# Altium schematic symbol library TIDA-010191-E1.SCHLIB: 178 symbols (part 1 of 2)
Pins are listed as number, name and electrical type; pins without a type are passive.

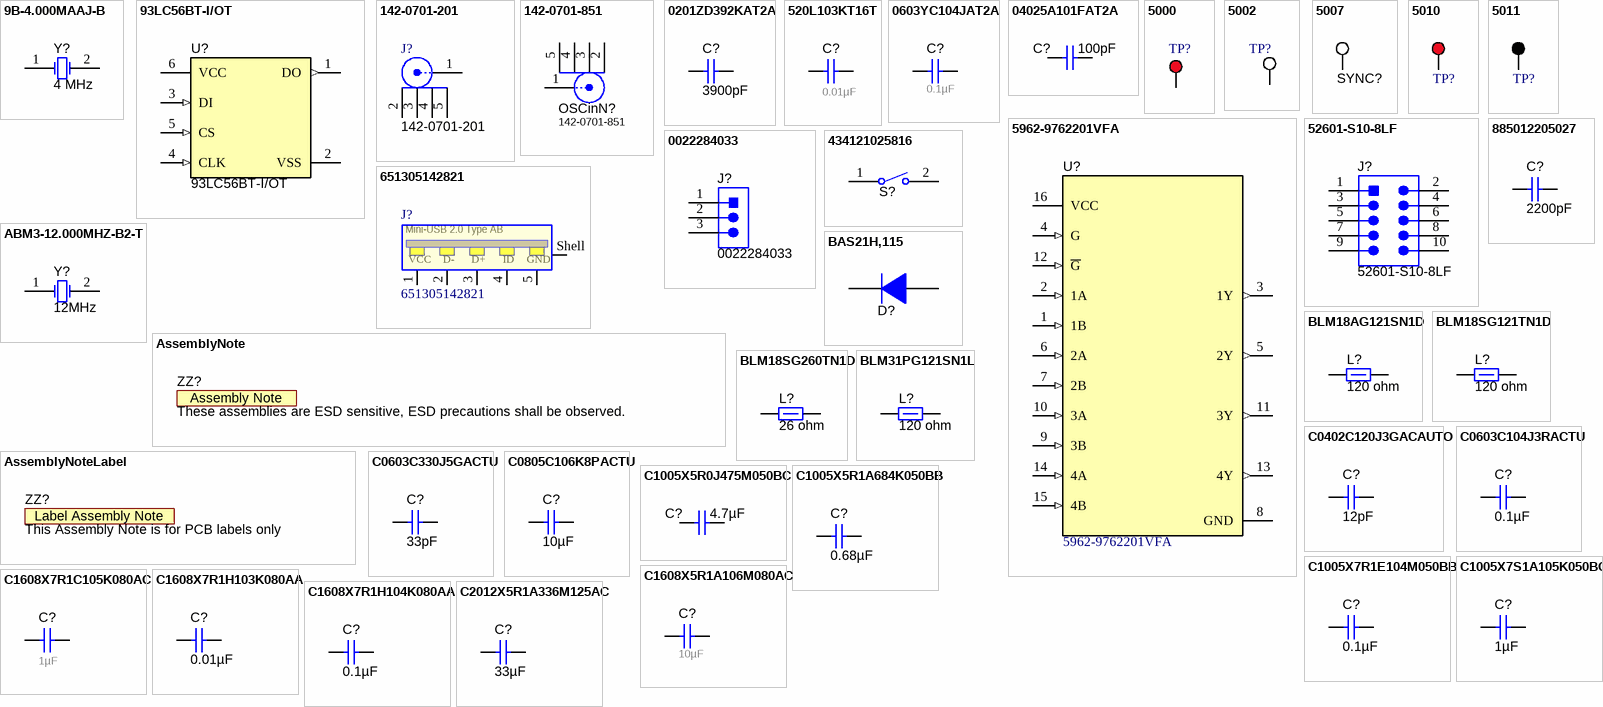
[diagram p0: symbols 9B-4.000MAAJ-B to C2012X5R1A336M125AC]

## 9B-4.000MAAJ-B
designator Y?  Frequency_Fixed: 4 MHz  (hidden comment: 9B-4.000MAAJ-B)
Crystal, 4 MHz, 18 pF, TH; Manufacturer: TXC Corporation; SymbolCreator: a0412235; SizeAreaWB_mm2: 94.5; SizeArea_mm2: 57.5; SizeX_mm: 11.5; SizeY_mm: 5; SizeZ_mm: 3.68; U/M: EA; TaMin_C: -20; TaMax_C: 70; Frequency Stability: ±30ppm
footprint TXC_9B
pins: 1 OSC1, 2 OSC2

## 93LC56BT-I/OT
designator U?
2K Microwire Compatible Serial EEPROM, SOT-23-6; Manufacturer: Microchip; SymbolCreator: x0208326; SizeAreaWB_mm2: 14.82; SizeArea_mm2: 8.12; SizeX_mm: 2.9; SizeY_mm: 2.8; SizeZ_mm: 1.15
footprint SOT-23-6
pins: 1 DO (out), 2 VSS (power), 3 DI (in), 4 CLK (in), 5 CS (in), 6 VCC (power)

## 142-0701-201
designator J?
Connector, TH, SMA; Manufacturer: Emerson Network Power; SymbolCreator: X0208326
footprint Johnson_142-0701-20x (Johnson Components recommended land pattern)
pins: 1, 2, 3, 4, 5

## 142-0701-851
designator OSCinN?
Connector, SMT, End launch SMA 50 ohm; Manufacturer: Emerson Network Power Connectivity; U/M: EA
footprint EMERSON_142-0701-851 (Johnson Components)
pins: 1, 2, 3, 4, 5

## 0201ZD392KAT2A
designator C?  ValueDisplayed: 3900pF  (hidden comment: 0201ZD392KAT2A)
CAP, CERM, 3900 pF, 10 V, +/- 10%, X5R, 0201; Manufacturer: AVX; Polarized: N; CompType: Capacitor; Value: 3900pF; U/M: EA; Cap_F: 0.0000000039; Tolerance_%: 10; Value1: Unknown; Value2: 10V; TaMin_C: -55; TaMax_C: 85; Cap_Case: 0201; SizeArea_mm2: 0.18; SizeAreaWB_mm2: 2.08; SizeX_mm: 0.6; SizeY_mm: 0.3; SizeZ_mm: 0.26; AEC Category: Q200
signal-integrity model Cap
simulation model Cap
footprint 0201
footprint 0201M
footprint 0201L
footprint 0201_Silk
pins: 1, 2

## 520L103KT16T
designator C?  ValueDisplayed: 0.01µF  (hidden comment: 520L103KT16T)
CAP, CERM, 0.01 µF, 16 V, +/- 10%, X7R, 0402; Manufacturer: AT Ceramics; Polarized: N; CompType: Capacitor; Value: 0.01uF; U/M: EA; Cap_F: 0.00000001; Tolerance_%: 10; Value1: Unknown; VDC_V: 16; Value2: 16V; TaMin_C: -55; TaMax_C: 125; Cap_Case: 0402; AEC Category: Q200; SizeArea_mm2: 0.5; SizeAreaWB_mm2: 3; SizeX_mm: 1; SizeZ_mm: 0.65
signal-integrity model Cap
simulation model Cap
footprint 0402_065
footprint 0402_065M
footprint 0402_065L
footprint 0402_065S
pins: 1, 2

## 0603YC104JAT2A
designator C?  ValueDisplayed: 0.1µF  (hidden comment: 0603YC104JAT2A)
CAP, CERM, 0.1uF, 16V, +/-5%, X7R, 0603; Manufacturer: AVX; Cap_Case: 0603; ESR_Ohm: 0.039; Polarized: N; TaMax_C: 125; TaMin_C: -55; Tolerance_%: 5; VDC_V: 16; Cap_F: 0.0000001; CompType: Capacitor; Value1: 0.039 ohm; U/M: EA
signal-integrity model Cap
simulation model Cap
footprint 0603
footprint 0603M
footprint 0603L
footprint 0603_HV
pins: 1, 2

## 04025A101FAT2A
designator C?  ValueDisplayed: 100pF  (hidden comment: 04025A101FAT2A)
CAP, CERM, 100 pF, 50 V, +/- 1%, C0G/NP0, 0402; Manufacturer: AVX; Polarized: N; CompType: Capacitor; Value: 100pF; U/M: EA; Cap_F: 0.0000000001; Tolerance_%: 1; Value1: Unknown; VDC_V: 50; Value2: 50V; TaMin_C: -55; TaMax_C: 125; Cap_Case: 0402; SizeArea_mm2: 0.5; SizeAreaWB_mm2: 3; SizeZ_mm: 0.6; AEC Category: Q200
signal-integrity model Cap
simulation model Cap
footprint 0402
footprint 0402M
footprint 0402L
footprint 0402S
pins: 1, 2

## 5000
designator TP?  (value not drawn)
Test Point, Miniature, Red, TH; Manufacturer: Keystone; CompType: Test Point Loop; ContactFinish: Silver
footprint Keystone5000
pins: 1

## 5002
designator TP?  (value not drawn)
Test Point, Miniature, White, TH; Manufacturer: Keystone; CompType: Test Point Loop; ContactFinish: Silver; Green_Lifecycle: Active; Green_REACh: Passed
footprint Keystone5002
pins: 1

## 5007
designator SYNC?  (value not drawn)
Test Point, Compact, White, TH; Manufacturer: Keystone; CompType: Test Point Loop; U/M: EA
footprint Keystone5007
pins: 1

## 5010
designator TP?  (value not drawn)
Test Point, Multipurpose, Red, TH; Manufacturer: Keystone; CompType: Test Point Loop; ContactFinish: Silver
footprint Keystone5010
pins: 1

## 5011
designator TP?  (value not drawn)
Test Point, Multipurpose, Black, TH; Manufacturer: Keystone; CompType: Test Point Loop; ContactFinish: Silver
footprint Keystone5011
pins: 1

## 5962-9762201VFA
designator U?
Quad LVDS Receiver, W0016A (CFP-16); Manufacturer: Texas Instruments; SizeZ_mm: 2.03; AEC Category: Q200; CompType: IC; AEC Qualified: N; Rating: Space
footprint W0016A_Custom_A (DFP, 16 Leads, Body 10.2x6.7mm, Pitch 1.27mm, Gullwing Leadform)
pins: 1 1B (in), 2 1A (in), 3 1Y (out), 4 G (in), 5 2Y (out), 6 2A (in), 7 2B (in), 8 GND (power), 9 3B (in), 10 3A (in), 11 3Y (out), 12 ~{G} (in), 13 4Y (out), 14 4A (in), 15 4B (in), 16 VCC (power)

## 52601-S10-8LF
designator J?
Header (shrouded), 100mil, 5x2, Gold, SMT; Manufacturer: FCI; SymbolCreator: a0412235
footprint FCI_52601-S10-8LF (FCI Electronics)
pins: 1, 2, 3, 4, 5, 6, 7, 8, 9, 10

## 0022284033
designator J?
Header, 2.54mm, 3x1, Tin, TH; Manufacturer: Molex; SymbolCreator: a0799628; Pitch_mm: 2.54; Gender: Male; Shrouded: N; Row_Count: 1; Current_A: 4; Voltage_V: 250; Cert_UL: Y
footprint Molex_0022284033
pins: 1, 2, 3
3 alternate drawings of the same symbol

## 434121025816
designator S?  (value not drawn)
Switch, Tactile, SPST, 12 V, SMD; Manufacturer: Wurth Elektronik; SymbolCreator: a0799628; VDC_V: 12; SwitchFunction: Off-On; PositionCount: 1; CurrentRating_mA: 50
footprint SW_434121025816
pins: 1, 2

## 651305142821
designator J?
WR-COM Mini USB 2.0 Type AB SMT Horizontal 5 Contacts
footprint 651305142821 (5 pins)
pins: 1 VCC, 2 D-, 3 D+, 4 ID, 5 GND, Shell

## 885012205027
designator C?  ValueDisplayed: 2200pF  (hidden comment: 885012205027)
CAP, CERM, 2200 pF, 16 V,+/- 10%, X7R, 0402; Manufacturer: Wurth Elektronik; Polarized: N; CompType: Capacitor; Value: 2200pF; U/M: EA; Cap_F: 0.0000000022; Tolerance_%: 10; VDC_V: 16; Value2: 16V; TaMin_C: -55; TaMax_C: 125; Cap_Case: 0402; AEC Category: Q200; SizeArea_mm2: 0.5; SizeAreaWB_mm2: 3; SizeX_mm: 1; SizeZ_mm: 0.6
signal-integrity model Cap
simulation model Cap
footprint 0402
footprint 0402M
footprint 0402L
footprint 0402S
pins: 1, 2

## ABM3-12.000MHZ-B2-T
designator Y?  Frequency: 12MHz  (hidden comment: ABM3-12.000MHZ-B2-T)
Crystal, 12Mhz, 18pF, SMD; Manufacturer: Abracon Corporation; SymbolCreator: a0412235; U/M: EA; TaMin_C: -20; TaMax_C: 70; Frequency Stability: ±50ppm
footprint XTAL_ABM3
pins: 1 OSC1, 2 OSC2

## AssemblyNote
designator ZZ?, comment These assemblies are ESD sensitive, ESD precautions shall be observed.  (no BOM)
SymbolCreator: codlsc; CompType: AssemblyNote
footprint AssemblyNote

## AssemblyNoteLabel
designator ZZ?, comment This Assembly Note is for PCB labels only  (no BOM)
SymbolCreator: a0412235
footprint AssemblyNoteLabel

## BAS21H,115
designator D?  (value not drawn)
Diode, Standard Recovery Rectifier, 200 V, 0.2 A, SOD-123F; Manufacturer: Nexperia; U/M: EA; Vf_V: 1.25; Value: 200V; Value1: 0.2A; Value2: 1.25V; Io_A: 0.2; Vr_V: 200; TJmax_C: 150; SizeAreaWB_mm2: 11.7; SizeArea_mm2: 5.6; SizeX_mm: 3.5; SizeY_mm: 1.6; SizeZ_mm: 1.1; AEC Category: Q101; AEC Qualified: N; Green_Lifecycle: Not Set; Green_REACh: Incomplete
signal-integrity model Diode
footprint SOD-123F
pins: 1 K, 2 A

## BLM18AG121SN1D
designator L?  ValueDisplayed: 120 ohm  (hidden comment: BLM18AG121SN1D)
Ferrite Bead, 120 ohm @ 100 MHz, 0.5 A, 0603; Manufacturer: MuRata; Value: 120 ohm; Imax_A: 0.5; DCR_ohm: 0.18; Value1: 0.18 ohm; Value2: 0.5A; SizeAreaWB_mm2: 4.68; SizeArea_mm2: 1.28; SizeX_mm: 1.6; SizeY_mm: 0.8; SizeZ_mm: 1; ZTyp@100MHz_Ohm: 120
footprint 0603
footprint 0603M
footprint 0603L
footprint 0603_HV
footprint 0603S
pins: 1, 2

## BLM18SG121TN1D
designator L?  ValueDisplayed: 120 ohm  (hidden comment: BLM18SG121TN1D)
Ferrite Bead, 120 ohm @ 100 MHz, 3 A, 0603; Manufacturer: MuRata; Value: 120 ohm; Imax_A: 3; DCR_ohm: 0.025; Value1: 0.025 ohm; Value2: 3A; SizeAreaWB_mm2: 4.68; SizeArea_mm2: 1.28; SizeX_mm: 1.6; SizeY_mm: 0.8; SizeZ_mm: 1; ZTyp@100MHz_Ohm: 120
footprint 0603
footprint 0603M
footprint 0603L
footprint 0603_HV
footprint 0603S
pins: 1, 2

## BLM18SG260TN1D
designator L?  ValueDisplayed: 26 ohm  (hidden comment: BLM18SG260TN1D)
Ferrite Bead, 26 ohm @ 100 MHz, 6 A, 0603; Manufacturer: MuRata; Value: 26 ohm; Imax_A: 6; DCR_ohm: 0.007; Value1: 0.007 ohm; Value2: 6A; SizeAreaWB_mm2: 4.68; SizeArea_mm2: 1.28; SizeX_mm: 1.6; SizeY_mm: 0.8; SizeZ_mm: 1; ZTyp@100MHz_Ohm: 26
footprint 0603
footprint 0603M
footprint 0603L
footprint 0603_HV
footprint 0603S
pins: 1, 2

## BLM31PG121SN1L
designator L?  ValueDisplayed: 120 ohm  (hidden comment: BLM31PG121SN1L)
Ferrite Bead, 120 ohm @ 100 MHz, 3.5 A, 1206; Manufacturer: MuRata; Value: 120 ohm; Imax_A: 3.5; DCR_ohm: 0.02; Value1: 0.02 ohm; Value2: 3.5A; SizeAreaWB_mm2: 10.92; SizeArea_mm2: 5.12; SizeX_mm: 3.2; SizeY_mm: 1.6; SizeZ_mm: 1.35; ZTyp@100MHz_Ohm: 120
footprint 1206
footprint 1206M
footprint 1206L
pins: 1, 2

## C0402C120J3GACAUTO
designator C?  ValueDisplayed: 12pF  (hidden comment: C0402C120J3GACAUTO)
CAP, CERM, 12 pF, 25 V, +/- 5%, C0G/NP0, AEC-Q200 Grade 1, 0402; Manufacturer: Kemet; Polarized: N; CompType: Capacitor; Value: 12pF; U/M: EA; Cap_F: 0.000000000012; Tolerance_%: 5; Value1: Unknown; VDC_V: 25; Value2: 25V; TaMin_C: -55; TaMax_C: 125; Cap_Case: 0402; SizeArea_mm2: 0.5; SizeAreaWB_mm2: 3; SizeX_mm: 1; SizeZ_mm: 0.6; AEC Category: Q200; AEC Qualified: Y
signal-integrity model Cap
simulation model Cap
footprint 0402
footprint 0402M
footprint 0402L
footprint 0402S
pins: 1, 2

## C0603C104J3RACTU
designator C?  ValueDisplayed: 0.1µF  (hidden comment: C0603C104J3RACTU)
CAP, CERM, 0.1uF, 25V, +/-5%, X7R, 0603; Manufacturer: Kemet; Cap_Case: 0603; Polarized: N; TaMax_C: 125; TaMin_C: -55; Tolerance_%: 5; VDC_V: 25; Cap_F: 0.0000001; CompType: Capacitor; Value1: Unknown; U/M: EA
signal-integrity model Cap
simulation model Cap
footprint 0603
footprint 0603M
footprint 0603L
footprint 0603_HV
pins: 1, 2

## C0603C330J5GACTU
designator C?  ValueDisplayed: 33pF  (hidden comment: C0603C330J5GACTU)
CAP, CERM, 33pF, 50V, +/-5%, C0G/NP0, 0603; Manufacturer: Kemet; Cap_Case: 0603; Polarized: N; TaMax_C: 125; TaMin_C: -55; Tolerance_%: 5; VDC_V: 50; Cap_F: 0.000000000033; CompType: Capacitor; U/M: EA; Value1: Unknown
signal-integrity model Cap
simulation model Cap
footprint 0603
footprint 0603M
footprint 0603L
footprint 0603_HV
pins: 1, 2

## C0805C106K8PACTU
designator C?  ValueDisplayed: 10µF  (hidden comment: C0805C106K8PACTU)
CAP, CERM, 10uF, 10V, +/-10%, X5R, 0805; Manufacturer: Kemet; Cap_Case: 0805; ESR_Ohm: 0.003; IRMS_A: 11.43; Polarized: N; TaMax_C: 85; TaMin_C: -55; Tolerance_%: 10; Cap_F: 0.00001; CompType: Capacitor; Value1: 0.003 ohm; U/M: EA
signal-integrity model Cap
simulation model Cap
footprint 0805_HV
footprint 0805
footprint 0805M
footprint 0805L
pins: 1, 2

## C1005X5R0J475M050BC
designator C?  ValueDisplayed: 4.7µF  (hidden comment: C1005X5R0J475M050BC)
CAP, CERM, 4.7 µF, 6.3 V, +/- 20%, X5R, 0402; Manufacturer: TDK; Polarized: N; CompType: Capacitor; Value: 4.7uF; U/M: EA; Cap_F: 0.0000047; Tolerance_%: 20; Value1: Unknown; VDC_V: 6.3; Value2: 6.3V; TaMin_C: -55; TaMax_C: 85; Cap_Case: 0402; SizeArea_mm2: 0.5; SizeAreaWB_mm2: 3; SizeX_mm: 1; SizeZ_mm: 0.6; AEC Category: Q200
signal-integrity model Cap
simulation model Cap
footprint 0402
footprint 0402M
footprint 0402L
footprint 0402S
pins: 1, 2

## C1005X5R1A684K050BB
designator C?  ValueDisplayed: 0.68µF  (hidden comment: C1005X5R1A684K050BB)
CAP, CERM, 0.68 µF, 10 V, +/- 10%, X5R, 0402; Manufacturer: TDK; Polarized: N; CompType: Capacitor; Value: 0.68uF; U/M: EA; Cap_F: 0.00000068; Tolerance_%: 10; Value1: Unknown; Value2: 10V; TaMin_C: -55; TaMax_C: 85; Cap_Case: 0402; SizeArea_mm2: 0.5; SizeAreaWB_mm2: 3; SizeX_mm: 1; SizeZ_mm: 0.6; AEC Category: Q200
signal-integrity model Cap
simulation model Cap
footprint 0402
footprint 0402M
footprint 0402L
footprint 0402S
pins: 1, 2

## C1005X7R1E104M050BB
designator C?  ValueDisplayed: 0.1µF  (hidden comment: C1005X7R1E104M050BB)
CAP, CERM, 0.1 µF, 25 V, +/- 20%, X7R, 0402; Manufacturer: TDK; Cap_Case: 0402; Polarized: N; TaMax_C: 125; TaMin_C: -55; Tolerance_%: 20; VDC_V: 25; Cap_F: 0.0000001; CompType: Capacitor; Value: 0.1uF; Value1: Unknown; Value2: 25V; U/M: EA; SizeArea_mm2: 0.5; SizeAreaWB_mm2: 3; SizeX_mm: 1; SizeZ_mm: 0.6; AEC Category: Q200
signal-integrity model Cap
simulation model Cap
footprint 0402
footprint 0402M
footprint 0402L
footprint 0402S
pins: 1, 2

## C1005X7S1A105K050BC
designator C?  ValueDisplayed: 1µF  (hidden comment: C1005X7S1A105K050BC)
CAP, CERM, 1 µF, 10 V, +/- 10%, X7S, 0402; Manufacturer: TDK; Polarized: N; CompType: Capacitor; Value: 1uF; U/M: EA; Cap_F: 0.000001; Tolerance_%: 10; ESR_ohm: 0.011416; Value1: 0.011416 ohm; Value2: 10V; IRMS_A: 1.483; TaMin_C: -55; TaMax_C: 125; Cap_Case: 0402; SizeArea_mm2: 0.5; SizeAreaWB_mm2: 3; SizeX_mm: 1; SizeZ_mm: 0.6; AEC Category: Q200
signal-integrity model Cap
simulation model Cap
footprint 0402
footprint 0402M
footprint 0402L
footprint 0402S
pins: 1, 2

## C1608X5R1A106M080AC
designator C?  ValueDisplayed: 10µF  (hidden comment: C1608X5R1A106M080AC)
CAP, CERM, 10 µF, 10 V, +/- 20%, X5R, 0603; Manufacturer: TDK; Cap_Case: 0603; ESR_ohm: 0.0078; IRMS_A: 1.85; Polarized: N; TaMax_C: 85; TaMin_C: -55; Tolerance_%: 20; VDC_V: 10; Cap_F: 0.00001; CompType: Capacitor; Value: 10uF; U/M: EA; Value1: 0.0078 ohm; Value2: 10V; AEC Category: Q200
signal-integrity model Cap
simulation model Cap
footprint 0603
footprint 0603M
footprint 0603L
footprint 0603_HV
footprint 0603S
pins: 1, 2

## C1608X7R1C105K080AC
designator C?  ValueDisplayed: 1µF  (hidden comment: C1608X7R1C105K080AC)
CAP, CERM, 1 µF, 16 V, +/- 10%, X7R, 0603; Manufacturer: TDK; Cap_Case: 0603; ESR_ohm: 0.0057; Polarized: N; TaMax_C: 125; TaMin_C: -55; Tolerance_%: 10; VDC_V: 16; Cap_F: 0.000001; CompType: Capacitor; Value: 1uF; Value1: 0.0057 ohm; Value2: 16V; U/M: EA; SizeArea_mm2: 1.28; SizeAreaWB_mm2: 4.68; SizeX_mm: 1.6; SizeY_mm: 0.8; SizeZ_mm: 1; AEC Category: Q200
signal-integrity model Cap
simulation model Cap
footprint 0603
footprint 0603M
footprint 0603L
footprint 0603_HV
footprint 0603S
pins: 1, 2

## C1608X7R1H103K080AA
designator C?  ValueDisplayed: 0.01µF  (hidden comment: C1608X7R1H103K080AA)
CAP, CERM, 0.01 µF, 50 V,+/- 10%, X7R, 0603; Manufacturer: TDK; Polarized: N; CompType: Capacitor; Value: 0.01uF; U/M: EA; Cap_F: 0.00000001; Tolerance_%: 10; ESR_ohm: 0.0539; Value1: 0.0539 ohm; VDC_V: 50; Value2: 50V; TaMin_C: -55; TaMax_C: 125; Cap_Case: 0603; SizeArea_mm2: 1.28; SizeAreaWB_mm2: 4.68; SizeX_mm: 1.6; SizeY_mm: 0.8; SizeZ_mm: 1; AEC Category: Q200; Green_Lifecycle: NRND; Green_REACh: Passed
signal-integrity model Cap
simulation model Cap
footprint 0603
footprint 0603M
footprint 0603L
footprint 0603_HV
footprint 0603S
pins: 1, 2

## C1608X7R1H104K080AA
designator C?  ValueDisplayed: 0.1µF  (hidden comment: C1608X7R1H104K080AA)
CAP, CERM, 0.1 µF, 50 V,+/- 10%, X7R, 0603; Manufacturer: TDK; Polarized: N; CompType: Capacitor; Value: 0.1uF; U/M: EA; Cap_F: 0.0000001; Tolerance_%: 10; ESR_ohm: 0.0296; Value1: 0.0296 ohm; VDC_V: 50; Value2: 50V; IRMS_A: 0.97199; TaMin_C: -55; TaMax_C: 125; Cap_Case: 0603; SizeArea_mm2: 1.28; SizeAreaWB_mm2: 4.68; SizeX_mm: 1.6; SizeY_mm: 0.8; SizeZ_mm: 1; AEC Category: Q200; Green_Lifecycle: NRND; Green_REACh: Passed
signal-integrity model Cap
simulation model Cap
footprint 0603
footprint 0603M
footprint 0603L
footprint 0603_HV
footprint 0603S
pins: 1, 2

## C2012X5R1A336M125AC
designator C?  ValueDisplayed: 33µF  (hidden comment: C2012X5R1A336M125AC)
CAP, CERM, 33 µF, 10 V, +/- 20%, X5R, 0805; Manufacturer: TDK; Polarized: N; CompType: Capacitor; Value: 33uF; U/M: EA; Cap_F: 0.000033; Tolerance_%: 20; ESR_ohm: 0.001694; Value1: 0.001694 ohm; VDC_V: 10; Value2: 10V; IRMS_A: 5.01281; TaMin_C: -55; TaMax_C: 85; Cap_Case: 0805; SizeArea_mm2: 2.5; SizeAreaWB_mm2: 6.75; SizeX_mm: 2; SizeY_mm: 1.25; SizeZ_mm: 1.45; AEC Category: Q200
signal-integrity model Cap
simulation model Cap
footprint 0805_HV
footprint 0805_HV1
footprint 0805
footprint 0805M
footprint 0805L
pins: 1, 2

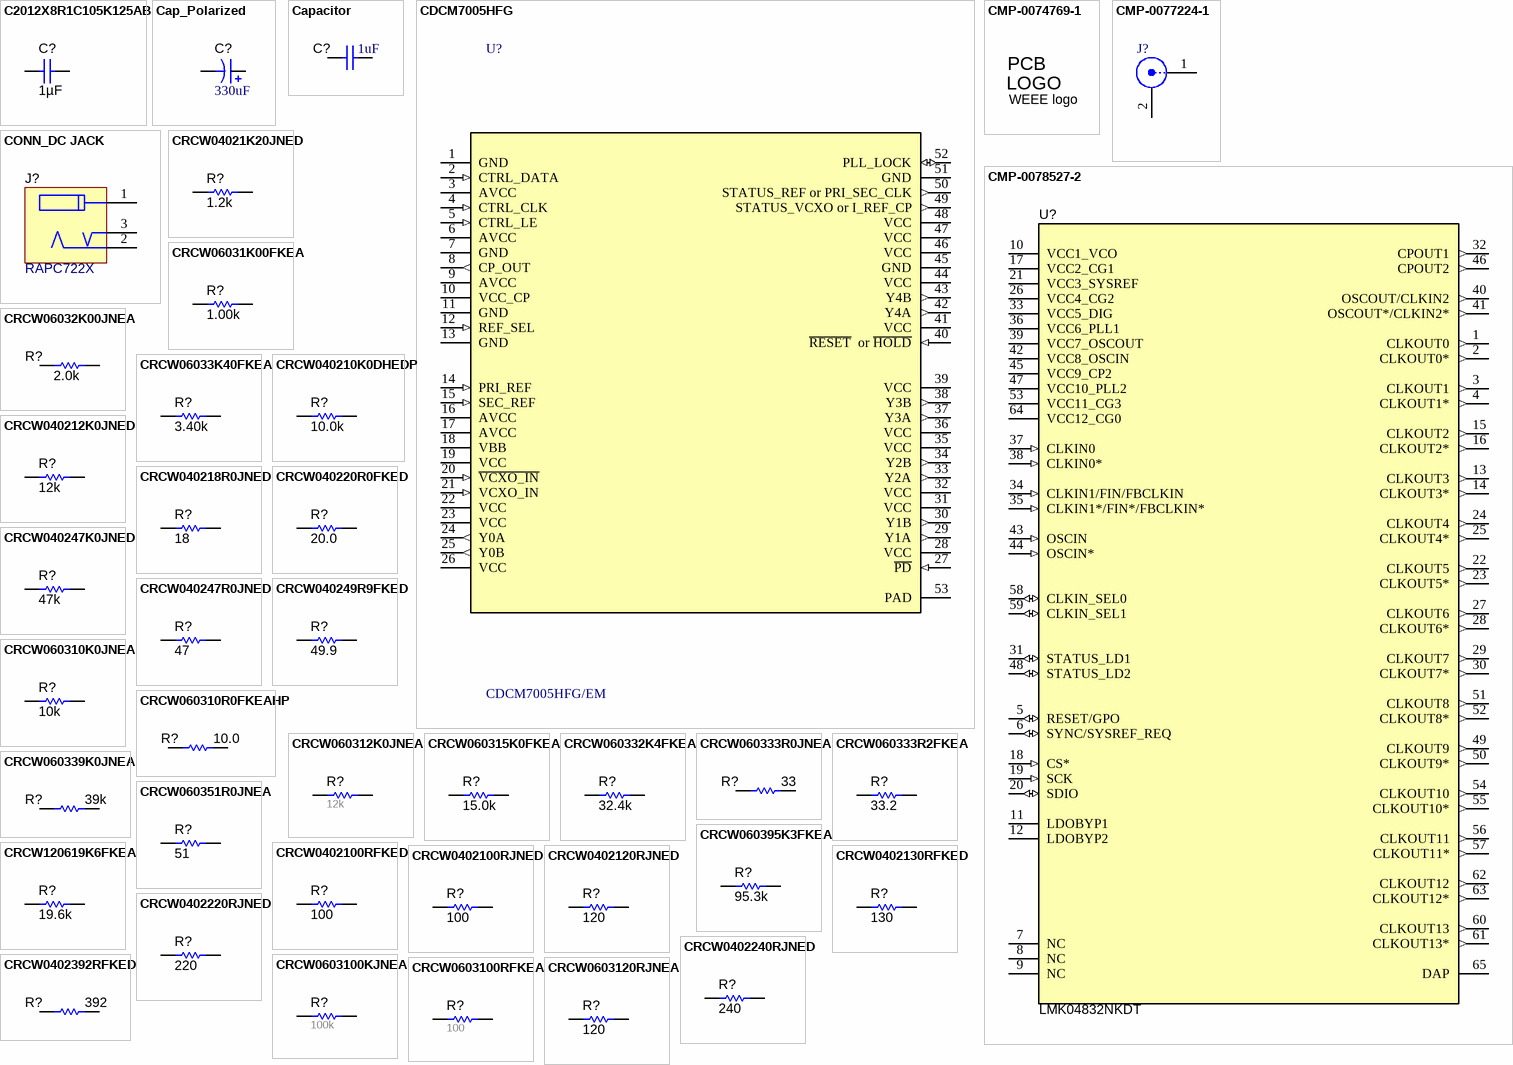
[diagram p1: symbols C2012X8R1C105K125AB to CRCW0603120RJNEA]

## C2012X8R1C105K125AB
designator C?  ValueDisplayed: 1µF  (hidden comment: C2012X8R1C105K125AB)
CAP, CERM, 1 µF, 16 V,+/- 10%, X8R, 0805; Manufacturer: TDK; Polarized: N; CompType: Capacitor; Value: 1uF; U/M: EA; Cap_F: 0.000001; Tolerance_%: 10; VDC_V: 16; Value2: 16V; TaMin_C: -55; TaMax_C: 150; Cap_Case: 0805; SizeArea_mm2: 2.5; SizeAreaWB_mm2: 6.75; SizeX_mm: 2; SizeY_mm: 1.25; SizeZ_mm: 1.45; AEC Category: Q200
signal-integrity model Cap
simulation model Cap
footprint 0805_HV
footprint 0805_HV1
footprint 0805
footprint 0805M
footprint 0805L
pins: 1, 2

## Cap_Polarized
designator C?, comment ValueDisplayed: 330uF  (hidden comment: T530X337M010ATE006)
CAP, Tantalum Polymer, 330 uF, 10 V, +/- 20%, 0.006 ohm, 7343-43 SMD; Manufacturer: Kemet; TaMin_C: -55°C; ESR_ohm: 6m; Polarized: Y; SizeAreaWB_mm2: 58.59; U/M: EA; Value: 330uF; TaMax_C: 125°C; SizeZ_mm: 4.3; SizeX_mm: 7.3; Value2: 10V; SizeArea_mm2: 31.39; CompType: Capacitor; AEC Qualified: N; Cap_F: 330µF; IRMS_A: 6.7A; AEC Category: Q200
footprint 7343-43 (Medium density IPC based on Kemet T495 series)
pins: 1 +, 2 -

## Capacitor
designator C?, comment ValueDisplayed: 1uF  (hidden comment: GRM155R6YA105KE11D)
CAP, CERM, 1 uF, 35 V, +/- 10%, X5R, 0402; Manufacturer: MuRata; TaMin_C: -55°C; Polarized: N; SizeAreaWB_mm2: 3; Value1: Unknown; U/M: EA; Value: 1uF; TaMax_C: 85°C; SizeZ_mm: 0.6; SizeX_mm: 1; SizeY_mm: 0.5; Cap_Case: 0402; Value2: 35V; CompType: Capacitor; Cap_F: 1µF; AEC Category: Q200
footprint 0402 (0402 from SM-752 data)
footprint 0402S (Based on C0402S footprint from PADS legacy)
footprint 0402L (0402 from SM-752 data)
footprint 0402M (0402 from SM-752 data)
pins: 1, 2

## CDCM7005HFG
designator U?, comment CDCM7005HFG/EM
3.3-V High Performance Rad-Tolerant Class V, Clock Synchronizer And Jitter Cleaner, HFG0052A (CFP-52); Manufacturer: Texas Instruments; SizeZ_mm: 2.68; AEC Category: Q200; AEC Qualified: N; CompType: IC
footprint HFG0052A_Custom_A (CFP-52)
pins: 1 GND (power), 2 CTRL_DATA (in), 3 AVCC (power), 4 CTRL_CLK (in), 5 CTRL_LE (in), 6 AVCC (power), 7 GND (power), 8 CP_OUT (out), 9 AVCC (power), 10 VCC_CP (power), 11 GND (power), 12 REF_SEL (in), 13 GND (power), 14 PRI_REF (in), 15 SEC_REF (in), 16 AVCC (power), 17 AVCC (power), 18 VBB (power), 19 VCC (power), 20 ~{VCXO_IN} (in), 21 VCXO_IN (in), 22 VCC (power), 23 VCC (power), 24 Y0A (out), 25 Y0B (out), 26 VCC (power), 27 ~{PD} (in), 28 VCC (power), 29 Y1A (out), 30 Y1B (out), 31 VCC (power), 32 VCC (power), 33 Y2A (out), 34 Y2B (out), 35 VCC (power), 36 VCC (power), 37 Y3A (out), 38 Y3B (out), 39 VCC (power), 40 ~{RESET}  or ~{HOLD} (in), 41 VCC (power), 42 Y4A (out), 43 Y4B (out), 44 VCC (power), 45 GND (power), 46 VCC (power), 47 VCC (power), 48 VCC (power), 49 STATUS_VCXO or I_REF_CP (out), 50 STATUS_REF or PRI_SEC_CLK (out), 51 GND (power), 52 PLL_LOCK (io), 53 PAD (power)
1 alternate drawing of the same symbol

## CMP-0074769-1
designator Logo?, comment WEEE logo  (no BOM)
footprint WEEE_Minimum (WEEElie bin)

## CMP-0077224-1
designator J?
Plug, 50 Ohm, Straight, SMT; PartNumber: 0853050232; Manufacturer: Molex; Cert_UL: Y; ContactFinish: Gold; CT: False; Gender: Male; Voltage_V: 335V
footprint Molex_0853050232 (Plug, 50 Ohm, Straight, SMT)
pins: 1, 2

## CMP-0078527-2
designator U?, comment LMK04832NKDT
Ultra Low-Noise JESD204B Compliant Clock Jitter Cleaner With Dual Loop PLLs, NKD0064A (WQFN-64); Manufacturer: Texas Instruments; AEC Qualified: N; SizeArea_mm2: 81; CompType: IC; SizeAreaWB_mm2: 121; AEC Category: Q200; SizeY_mm: 9; SizeZ_mm: 0.8
footprint NKD0064A (QFN, 64-Leads, Body 9x9mm, Pitch 0.5mm)
pins: 1 CLKOUT0 (out), 2 CLKOUT0* (out), 3 CLKOUT1 (out), 4 CLKOUT1* (out), 5 RESET/GPO (io), 6 SYNC/SYSREF_REQ (io), 7 NC, 8 NC, 9 NC, 10 VCC1_VCO (power), 11 LDOBYP1, 12 LDOBYP2, 13 CLKOUT3 (out), 14 CLKOUT3* (out), 15 CLKOUT2 (out), 16 CLKOUT2* (out), 17 VCC2_CG1 (power), 18 CS* (in), 19 SCK (in), 20 SDIO (io), 21 VCC3_SYSREF (power), 22 CLKOUT5 (out), 23 CLKOUT5* (out), 24 CLKOUT4 (out), 25 CLKOUT4* (out), 26 VCC4_CG2 (power), 27 CLKOUT6 (out), 28 CLKOUT6* (out), 29 CLKOUT7 (out), 30 CLKOUT7* (out), 31 STATUS_LD1 (io), 32 CPOUT1 (out), 33 VCC5_DIG (power), 34 CLKIN1/FIN/FBCLKIN (in), 35 CLKIN1*/FIN*/FBCLKIN* (in), 36 VCC6_PLL1 (power), 37 CLKIN0 (in), 38 CLKIN0* (in), 39 VCC7_OSCOUT (power), 40 OSCOUT/CLKIN2 (out), 41 OSCOUT*/CLKIN2* (out), 42 VCC8_OSCIN (power), 43 OSCIN (in), 44 OSCIN* (in), 45 VCC9_CP2 (power), 46 CPOUT2 (out), 47 VCC10_PLL2 (power), 48 STATUS_LD2 (io), 49 CLKOUT9 (out), 50 CLKOUT9* (out), 51 CLKOUT8 (out), 52 CLKOUT8* (out), 53 VCC11_CG3 (power), 54 CLKOUT10 (out), 55 CLKOUT10* (out), 56 CLKOUT11 (out), 57 CLKOUT11* (out), 58 CLKIN_SEL0 (io), 59 CLKIN_SEL1 (io), 60 CLKOUT13 (out), 61 CLKOUT13* (out), 62 CLKOUT12 (out), 63 CLKOUT12* (out), 64 VCC12_CG0 (power), 65 DAP (power)

## CONN_DC JACK
designator J?, comment RAPC722X
Power Jack, mini, 2.1mm OD, R/A, TH; Manufacturer: Switchcraft; CNHeader: False; Green_Lifecycle: Not Set; Green_REACh: Incomplete
footprint CONN_RAPC722X (Conn_DC Jack)
pins: 1, 2, 3

## CRCW04021K20JNED
designator R?  ValueDisplayed: 1.2k  (hidden comment: CRCW04021K20JNED)
RES, 1.2 k, 5%, 0.063 W, 0402; Manufacturer: Vishay-Dale; CompType: Resistor; Value: 1.2k; Res_ohm: 1200; Value_Code: 1k20; Tolerance_%: 5; Power_W: 0.063; Value2: 0.063W; VDC_V: 50; TempCo: 200 ppm/C; SizeArea_mm2: 0.5; SizeX_mm: 1; SizeZ_mm: 0.6; EIA_Code: E24; U/M: EA; AEC Category: Q200; Green_Lifecycle: Active; Green_REACh: Passed
signal-integrity model Resistor
simulation model Resistor
footprint 0402
footprint 0402M
footprint 0402L
footprint 0402S
pins: 1, 2

## CRCW06031K00FKEA
designator R?  ValueDisplayed: 1.00k  (hidden comment: CRCW06031K00FKEA)
RES, 1.00 k, 1%, 0.1 W, 0603; Manufacturer: Vishay-Dale; CompType: Resistor; Value: 1.00k; Res_ohm: 1000; Value_Code: 1k00; Tolerance_%: 1; Power_W: 0.1; Value2: 0.1W; VDC_V: 75; TempCo: 100 ppm/C; SizeArea_mm2: 1.28; SizeX_mm: 1.6; SizeY_mm: 0.8; EIA_Code: E96; U/M: EA; AEC Category: Q200
signal-integrity model Resistor
simulation model Resistor
footprint 0603
footprint 0603M
footprint 0603L
footprint 0603_HV
footprint 0603S
pins: 1, 2

## CRCW06032K00JNEA
designator R?  ValueDisplayed: 2.0k  (hidden comment: CRCW06032K00JNEA)
RES, 2.0 k, 5%, 0.1 W, 0603; Manufacturer: Vishay-Dale; CompType: Resistor; Value: 2.0k; Res_ohm: 2000; Value_Code: 2k00; Tolerance_%: 5; Power_W: 0.1; Value2: 0.1W; VDC_V: 75; TempCo: 200 ppm/C; SizeArea_mm2: 1.28; SizeX_mm: 1.6; SizeY_mm: 0.8; SizeZ_mm: 1; EIA_Code: E24; U/M: EA; AEC Category: Q200
signal-integrity model Resistor
simulation model Resistor
footprint 0603
footprint 0603M
footprint 0603L
footprint 0603_HV
footprint 0603S
pins: 1, 2

## CRCW06033K40FKEA
designator R?  ValueDisplayed: 3.40k  (hidden comment: CRCW06033K40FKEA)
RES, 3.40 k, 1%, 0.1 W, 0603; Manufacturer: Vishay-Dale; CompType: Resistor; Value: 3.40k; Res_ohm: 3400; Value_Code: 3k40; Tolerance_%: 1; Power_W: 0.1; Value2: 0.1W; VDC_V: 75; TempCo: 100 ppm/C; SizeArea_mm2: 1.28; SizeX_mm: 1.6; SizeY_mm: 0.8; EIA_Code: E96; U/M: EA; AEC Category: Q200; Green_Lifecycle: Active; Green_REACh: Passed
signal-integrity model Resistor
simulation model Resistor
footprint 0603
footprint 0603M
footprint 0603L
footprint 0603_HV
footprint 0603S
pins: 1, 2

## CRCW040210K0DHEDP
designator R?  ValueDisplayed: 10.0k  (hidden comment: CRCW040210K0DHEDP)
RES, 10.0 k, 0.5%, 0.063 W, 0402; Manufacturer: Vishay-Dale; CompType: Resistor; Value: 10.0k; Res_ohm: 10000; Value_Code: 10k0; Tolerance_%: 0.5; Power_W: 0.063; Value2: 0.063W; VDC_V: 50; TempCo: 50 ppm/C; SizeX_mm: 1; SizeZ_mm: 0.6; EIA_Code: E192; U/M: EA; AEC Category: Q200
signal-integrity model Resistor
simulation model Resistor
footprint 0402
footprint 0402M
footprint 0402L
footprint 0402S
pins: 1, 2

## CRCW040212K0JNED
designator R?  ValueDisplayed: 12k  (hidden comment: CRCW040212K0JNED)
RES, 12 k, 5%, 0.063 W, 0402; Manufacturer: Vishay-Dale; CompType: Resistor; Value: 12k; Res_ohm: 12000; Value_Code: 12k0; Tolerance_%: 5; Power_W: 0.063; Value2: 0.063W; VDC_V: 50; TempCo: 200 ppm/C; EIA_Code: E24; U/M: EA; AEC Category: Q200
signal-integrity model Resistor
simulation model Resistor
footprint 0402
footprint 0402M
footprint 0402L
footprint 0402S
pins: 1, 2

## CRCW040218R0JNED
designator R?  ValueDisplayed: 18  (hidden comment: CRCW040218R0JNED)
RES, 18, 5%, 0.063 W, 0402; Manufacturer: Vishay-Dale; CompType: Resistor; Value: 18; Value_Code: 18R0; Tolerance_%: 5; Power_W: 0.063; Value2: 0.063W; VDC_V: 50; TempCo: 200 ppm/C; EIA_Code: E24; U/M: EA; AEC Category: Q200
signal-integrity model Resistor
simulation model Resistor
footprint 0402
footprint 0402M
footprint 0402L
footprint 0402S
pins: 1, 2

## CRCW040220R0FKED
designator R?  ValueDisplayed: 20.0  (hidden comment: CRCW040220R0FKED)
RES, 20.0, 1%, 0.063 W, 0402; Manufacturer: Vishay-Dale; CompType: Resistor; Value: 20.0; Res_ohm: 20; Value_Code: 20R0; Tolerance_%: 1; Power_W: 0.063; Value2: 0.063W; VDC_V: 50; TempCo: 100 ppm/C; SizeArea_mm2: 0.5; SizeZ_mm: 0.6; EIA_Code: E96; U/M: EA; AEC Category: Q200
signal-integrity model Resistor
simulation model Resistor
footprint 0402
footprint 0402M
footprint 0402L
footprint 0402S
pins: 1, 2

## CRCW040247K0JNED
designator R?  ValueDisplayed: 47k  (hidden comment: CRCW040247K0JNED)
RES, 47 k, 5%, 0.063 W, 0402; Manufacturer: Vishay-Dale; CompType: Resistor; Value: 47k; Res_ohm: 47000; Value_Code: 47k0; Tolerance_%: 5; Power_W: 0.063; Value2: 0.063W; VDC_V: 50; TempCo: 200 ppm/C; EIA_Code: E24; U/M: EA; AEC Category: Q200; SizeArea_mm2: 0.5; SizeX_mm: 1; SizeZ_mm: 0.6; Green_Lifecycle: Active; Green_REACh: Passed
signal-integrity model Resistor
simulation model Resistor
footprint 0402
footprint 0402M
footprint 0402L
footprint 0402S
pins: 1, 2

## CRCW040247R0JNED
designator R?  ValueDisplayed: 47  (hidden comment: CRCW040247R0JNED)
RES, 47, 5%, 0.063 W, 0402; Manufacturer: Vishay-Dale; CompType: Resistor; Value: 47; Value_Code: 47R0; Tolerance_%: 5; Power_W: 0.063; Value2: 0.063W; VDC_V: 50; TempCo: 200 ppm/C; SizeArea_mm2: 0.5; SizeX_mm: 1; SizeZ_mm: 0.6; EIA_Code: E24; U/M: EA; AEC Category: Q200
signal-integrity model Resistor
simulation model Resistor
footprint 0402
footprint 0402M
footprint 0402L
footprint 0402S
pins: 1, 2

## CRCW040249R9FKED
designator R?  ValueDisplayed: 49.9  (hidden comment: CRCW040249R9FKED)
RES, 49.9, 1%, 0.063 W, 0402; Manufacturer: Vishay-Dale; CompType: Resistor; Value: 49.9; Value_Code: 49R9; Tolerance_%: 1; Power_W: 0.063; Value2: 0.063W; VDC_V: 50; TempCo: 100 ppm/C; EIA_Code: E96; U/M: EA; AEC Category: Q200
signal-integrity model Resistor
simulation model Resistor
footprint 0402
footprint 0402M
footprint 0402L
footprint 0402S
pins: 1, 2

## CRCW060310K0JNEA
designator R?  ValueDisplayed: 10k  (hidden comment: CRCW060310K0JNEA)
RES, 10 k, 5%, 0.1 W, 0603; Manufacturer: Vishay-Dale; CompType: Resistor; Value: 10k; Res_ohm: 10000; Value_Code: 10k0; Tolerance_%: 5; Power_W: 0.1; Value2: 0.1W; VDC_V: 75; TempCo: 200 ppm/C; SizeArea_mm2: 1.28; SizeX_mm: 1.6; SizeY_mm: 0.8; SizeZ_mm: 1; EIA_Code: E24; U/M: EA; AEC Category: Q200
signal-integrity model Resistor
simulation model Resistor
footprint 0603
footprint 0603M
footprint 0603L
footprint 0603_HV
footprint 0603S
pins: 1, 2

## CRCW060310R0FKEAHP
designator R?  ValueDisplayed: 10.0  (hidden comment: CRCW060310R0FKEAHP)
RES, 10.0, 1%, 0.25 W, 0603; Manufacturer: Vishay-Dale; CompType: Resistor; Value: 10.0; Res_ohm: 10; Value_Code: 10R0; Tolerance_%: 1; Power_W: 0.25; Value2: 0.25W; VDC_V: 75; TempCo: 100 ppm/C; SizeArea_mm2: 1.28; SizeX_mm: 1.6; SizeY_mm: 0.8; EIA_Code: E96; U/M: EA; AEC Category: Q200
signal-integrity model Resistor
simulation model Resistor
footprint 0603
footprint 0603M
footprint 0603L
footprint 0603_HV
footprint 0603S
pins: 1, 2

## CRCW060312K0JNEA
designator R?  value 12k  (hidden comment: CRCW060312K0JNEA)
RES, 12k ohm, 5%, 0.1W, 0603; Manufacturer: Vishay-Dale; CompType: Resistor; Tolerance_%: 5; VDC_V: 75; Power_W: 0.1; Res_ohm: 12000; U/M: EA; Value_Code: 12k0; EIA_Code: E24
signal-integrity model Resistor
simulation model Resistor
footprint 0603
footprint 0603M
footprint 0603L
footprint 0603_HV
pins: 1, 2

## CRCW060315K0FKEA
designator R?  ValueDisplayed: 15.0k  (hidden comment: CRCW060315K0FKEA)
RES, 15.0 k, 1%, 0.1 W, 0603; Manufacturer: Vishay-Dale; CompType: Resistor; Value: 15.0k; Res_ohm: 15000; Value_Code: 15k0; Tolerance_%: 1; Power_W: 0.1; Value2: 0.1W; VDC_V: 75; TempCo: 100 ppm/C; SizeArea_mm2: 1.28; SizeX_mm: 1.6; SizeY_mm: 0.8; EIA_Code: E96; U/M: EA; AEC Category: Q200; Green_Lifecycle: Active; Green_REACh: Passed
signal-integrity model Resistor
simulation model Resistor
footprint 0603
footprint 0603M
footprint 0603L
footprint 0603_HV
footprint 0603S
pins: 1, 2

## CRCW060332K4FKEA
designator R?  ValueDisplayed: 32.4k  (hidden comment: CRCW060332K4FKEA)
RES, 32.4 k, 1%, 0.1 W, 0603; Manufacturer: Vishay-Dale; CompType: Resistor; Value: 32.4k; Res_ohm: 32400; Value_Code: 32k4; Tolerance_%: 1; Power_W: 0.1; Value2: 0.1W; VDC_V: 75; TempCo: 100 ppm/C; SizeArea_mm2: 1.28; SizeX_mm: 1.6; SizeY_mm: 0.8; EIA_Code: E96; U/M: EA; AEC Category: Q200; Green_Lifecycle: Active; Green_REACh: Passed
signal-integrity model Resistor
simulation model Resistor
footprint 0603
footprint 0603M
footprint 0603L
footprint 0603_HV
footprint 0603S
pins: 1, 2

## CRCW060333R0JNEA
designator R?  ValueDisplayed: 33  (hidden comment: CRCW060333R0JNEA)
RES, 33, 5%, 0.1 W, 0603; Manufacturer: Vishay-Dale; CompType: Resistor; Value: 33; Value_Code: 33R0; Tolerance_%: 5; Power_W: 0.1; Value2: 0.1W; VDC_V: 75; TempCo: 200 ppm/C; SizeArea_mm2: 1.28; SizeX_mm: 1.6; SizeY_mm: 0.8; SizeZ_mm: 1; EIA_Code: E24; U/M: EA; AEC Category: Q200
signal-integrity model Resistor
simulation model Resistor
footprint 0603
footprint 0603M
footprint 0603L
footprint 0603_HV
footprint 0603S
pins: 1, 2

## CRCW060333R2FKEA
designator R?  ValueDisplayed: 33.2  (hidden comment: CRCW060333R2FKEA)
RES, 33.2, 1%, 0.1 W, 0603; Manufacturer: Vishay-Dale; CompType: Resistor; Value: 33.2; Value_Code: 33R2; Tolerance_%: 1; Power_W: 0.1; Value2: 0.1W; VDC_V: 75; TempCo: 100 ppm/C; SizeArea_mm2: 1.28; SizeX_mm: 1.6; SizeY_mm: 0.8; EIA_Code: E96; U/M: EA; AEC Category: Q200
signal-integrity model Resistor
simulation model Resistor
footprint 0603
footprint 0603M
footprint 0603L
footprint 0603_HV
footprint 0603S
pins: 1, 2

## CRCW060339K0JNEA
designator R?  ValueDisplayed: 39k  (hidden comment: CRCW060339K0JNEA)
RES, 39 k, 5%, 0.1 W, 0603; Manufacturer: Vishay-Dale; CompType: Resistor; Value: 39k; Res_ohm: 39000; Value_Code: 39k0; Tolerance_%: 5; Power_W: 0.1; Value2: 0.1W; VDC_V: 75; TempCo: 200 ppm/C; SizeArea_mm2: 1.28; SizeX_mm: 1.6; SizeY_mm: 0.8; SizeZ_mm: 1; EIA_Code: E24; U/M: EA; AEC Category: Q200
signal-integrity model Resistor
simulation model Resistor
footprint 0603
footprint 0603M
footprint 0603L
footprint 0603_HV
footprint 0603S
pins: 1, 2

## CRCW060351R0JNEA
designator R?  value 51  (hidden comment: CRCW060351R0JNEA)
RES, 51 ohm, 5%, 0.1W, 0603; Manufacturer: Vishay-Dale; CompType: Resistor; Tolerance_%: 5; VDC_V: 75; Power_W: 0.1; Value_Code: 51R0; EIA_Code: E24; TempCo: 200 ppm/C; U/M: EA
signal-integrity model Resistor
simulation model Resistor
footprint 0603
footprint 0603M
footprint 0603L
footprint 0603_HV
pins: 1, 2

## CRCW060395K3FKEA
designator R?  ValueDisplayed: 95.3k  (hidden comment: CRCW060395K3FKEA)
RES, 95.3 k, 1%, 0.1 W, 0603; Manufacturer: Vishay-Dale; CompType: Resistor; Value: 95.3k; Res_ohm: 95300; Value_Code: 95k3; Tolerance_%: 1; Power_W: 0.1; Value2: 0.1W; VDC_V: 75; TempCo: 100 ppm/C; SizeArea_mm2: 1.28; SizeX_mm: 1.6; SizeY_mm: 0.8; EIA_Code: E96; U/M: EA; AEC Category: Q200; Green_Lifecycle: Active; Green_REACh: Passed
signal-integrity model Resistor
simulation model Resistor
footprint 0603
footprint 0603M
footprint 0603L
footprint 0603_HV
footprint 0603S
pins: 1, 2

## CRCW120619K6FKEA
designator R?  ValueDisplayed: 19.6k  (hidden comment: CRCW120619K6FKEA)
RES, 19.6 k, 1%, 0.25 W, 1206; Manufacturer: Vishay-Dale; CompType: Resistor; Value: 19.6k; Res_ohm: 19600; Value_Code: 19k6; Tolerance_%: 1; Power_W: 0.25; Value2: 0.25W; VDC_V: 200; TempCo: 100 ppm/C; SizeArea_mm2: 5.12; SizeX_mm: 3.2; SizeY_mm: 1.6; SizeZ_mm: 1.35; EIA_Code: E96; U/M: EA; AEC Category: Q200; Green_Lifecycle: Active; Green_REACh: Passed
signal-integrity model Resistor
simulation model Resistor
footprint 1206
footprint 1206M
footprint 1206L
pins: 1, 2

## CRCW0402100RFKED
designator R?  ValueDisplayed: 100  (hidden comment: CRCW0402100RFKED)
RES, 100, 1%, 0.063 W, 0402; Manufacturer: Vishay-Dale; CompType: Resistor; Value: 100; Value_Code: 100R; Tolerance_%: 1; Power_W: 0.063; Value2: 0.063W; VDC_V: 50; TempCo: 100 ppm/C; EIA_Code: E96; U/M: EA; AEC Category: Q200; SizeArea_mm2: 0.5; SizeZ_mm: 0.6
signal-integrity model Resistor
simulation model Resistor
footprint 0402
footprint 0402M
footprint 0402L
footprint 0402S
pins: 1, 2

## CRCW0402100RJNED
designator R?  ValueDisplayed: 100  (hidden comment: CRCW0402100RJNED)
RES, 100, 5%, 0.063 W, 0402; Manufacturer: Vishay-Dale; CompType: Resistor; Value: 100; Value_Code: 100R; Tolerance_%: 5; Power_W: 0.063; Value2: 0.063W; VDC_V: 50; TempCo: 200 ppm/C; SizeArea_mm2: 0.5; SizeX_mm: 1; SizeZ_mm: 0.6; EIA_Code: E24; U/M: EA; AEC Category: Q200
signal-integrity model Resistor
simulation model Resistor
footprint 0402
footprint 0402M
footprint 0402L
footprint 0402S
pins: 1, 2

## CRCW0402120RJNED
designator R?  ValueDisplayed: 120  (hidden comment: CRCW0402120RJNED)
RES, 120, 5%, 0.063 W, 0402; Manufacturer: Vishay-Dale; CompType: Resistor; Value: 120; Value_Code: 120R; Tolerance_%: 5; Power_W: 0.063; Value2: 0.063W; VDC_V: 50; TempCo: 200 ppm/C; SizeArea_mm2: 0.5; SizeX_mm: 1; SizeZ_mm: 0.6; EIA_Code: E24; U/M: EA; AEC Category: Q200
signal-integrity model Resistor
simulation model Resistor
footprint 0402
footprint 0402M
footprint 0402L
footprint 0402S
pins: 1, 2

## CRCW0402130RFKED
designator R?  ValueDisplayed: 130  (hidden comment: CRCW0402130RFKED)
RES, 130, 1%, 0.063 W, 0402; Manufacturer: Vishay-Dale; CompType: Resistor; Value: 130; Value_Code: 130R; Tolerance_%: 1; Power_W: 0.063; Value2: 0.063W; VDC_V: 50; TempCo: 100 ppm/C; SizeArea_mm2: 0.5; SizeZ_mm: 0.6; EIA_Code: E96; U/M: EA; AEC Category: Q200
signal-integrity model Resistor
simulation model Resistor
footprint 0402
footprint 0402M
footprint 0402L
footprint 0402S
pins: 1, 2

## CRCW0402220RJNED
designator R?  ValueDisplayed: 220  (hidden comment: CRCW0402220RJNED)
RES, 220, 5%, 0.063 W, 0402; Manufacturer: Vishay-Dale; CompType: Resistor; Value: 220; Value_Code: 220R; Tolerance_%: 5; Power_W: 0.063; Value2: 0.063W; VDC_V: 50; TempCo: 200 ppm/C; SizeArea_mm2: 0.5; SizeX_mm: 1; SizeZ_mm: 0.6; EIA_Code: E24; U/M: EA; AEC Category: Q200
signal-integrity model Resistor
simulation model Resistor
footprint 0402
footprint 0402M
footprint 0402L
footprint 0402S
pins: 1, 2

## CRCW0402240RJNED
designator R?  ValueDisplayed: 240  (hidden comment: CRCW0402240RJNED)
RES, 240, 5%, 0.063 W, 0402; Manufacturer: Vishay-Dale; CompType: Resistor; Value: 240; Value_Code: 240R; Tolerance_%: 5; Power_W: 0.063; Value2: 0.063W; VDC_V: 50; TempCo: 200 ppm/C; SizeArea_mm2: 0.5; SizeX_mm: 1; SizeZ_mm: 0.6; EIA_Code: E24; U/M: EA; AEC Category: Q200
signal-integrity model Resistor
simulation model Resistor
footprint 0402
footprint 0402M
footprint 0402L
footprint 0402S
pins: 1, 2

## CRCW0402392RFKED
designator R?  ValueDisplayed: 392  (hidden comment: CRCW0402392RFKED)
RES, 392, 1%, 0.063 W, 0402; Manufacturer: Vishay-Dale; CompType: Resistor; Value: 392; Value_Code: 392R; Tolerance_%: 1; Power_W: 0.063; Value2: 0.063W; VDC_V: 50; TempCo: 100 ppm/C; SizeArea_mm2: 0.5; SizeZ_mm: 0.6; EIA_Code: E96; U/M: EA; AEC Category: Q200; Green_Lifecycle: Active; Green_REACh: Passed
signal-integrity model Resistor
simulation model Resistor
footprint 0402
footprint 0402M
footprint 0402L
footprint 0402S
pins: 1, 2

## CRCW0603100KJNEA
designator R?  ValueDisplayed: 100k  (hidden comment: CRCW0603100KJNEA)
RES, 100 k, 5%, 0.1 W, 0603; Manufacturer: Vishay-Dale; CompType: Resistor; Tolerance_%: 5; VDC_V: 75; Power_W: 0.1; Res_ohm: 100000; Value: 100k; U/M: EA; Value2: 0.1W; EIA_Code: E24; TempCo: 200 ppm/C; SizeArea_mm2: 1.28; SizeX_mm: 1.6; SizeY_mm: 0.8; SizeZ_mm: 1; AEC Category: Q200
signal-integrity model Resistor
simulation model Resistor
footprint 0603
footprint 0603M
footprint 0603L
footprint 0603_HV
footprint 0603S
pins: 1, 2

## CRCW0603100RFKEA
designator R?  ValueDisplayed: 100  (hidden comment: CRCW0603100RFKEA)
RES, 100, 1%, 0.1 W, 0603; Manufacturer: Vishay-Dale; CompType: Resistor; Tolerance_%: 1; VDC_V: 75; Power_W: 0.1; Value: 100; U/M: EA; Value_Code: 100R; Value2: 0.1W; EIA_Code: E96; TempCo: 100 ppm/C; SizeArea_mm2: 1.28; SizeX_mm: 1.6; SizeY_mm: 0.8; AEC Category: Q200
signal-integrity model Resistor
simulation model Resistor
footprint 0603
footprint 0603M
footprint 0603L
footprint 0603_HV
footprint 0603S
pins: 1, 2

## CRCW0603120RJNEA
designator R?  ValueDisplayed: 120  (hidden comment: CRCW0603120RJNEA)
RES, 120, 5%, 0.1 W, 0603; Manufacturer: Vishay-Dale; CompType: Resistor; Tolerance_%: 5; VDC_V: 75; Power_W: 0.1; Value: 120; U/M: EA; Value_Code: 120R; Value2: 0.1W; TempCo: 200 ppm/C; EIA_Code: E24; SizeArea_mm2: 1.28; SizeX_mm: 1.6; SizeY_mm: 0.8; SizeZ_mm: 1; AEC Category: Q200; Green_Lifecycle: Active; Green_REACh: Passed
signal-integrity model Resistor
simulation model Resistor
footprint 0603
footprint 0603M
footprint 0603L
footprint 0603_HV
footprint 0603S
pins: 1, 2

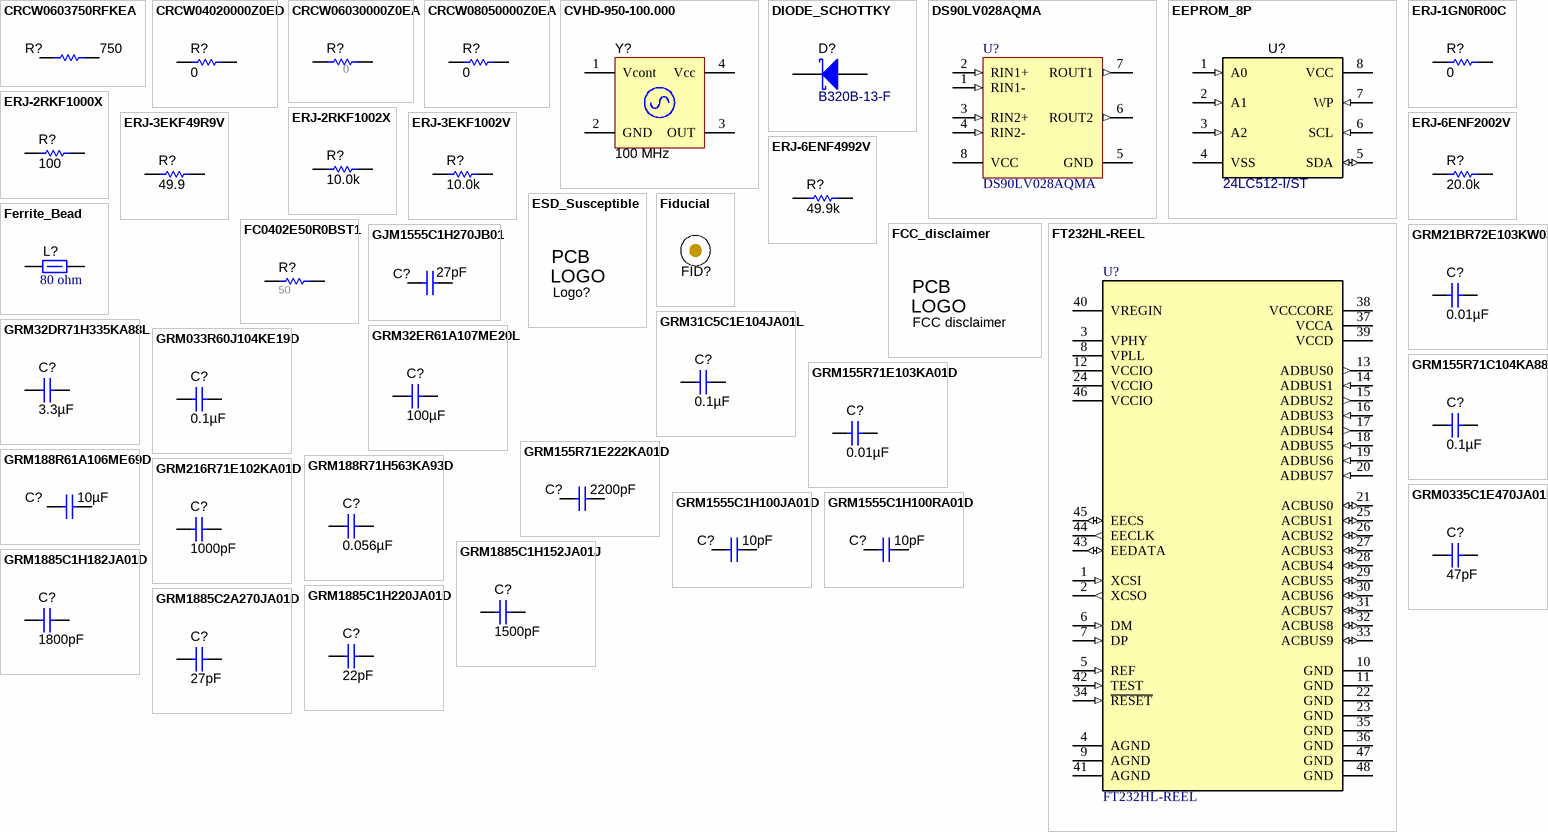
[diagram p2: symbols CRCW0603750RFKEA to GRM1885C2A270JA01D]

## CRCW0603750RFKEA
designator R?  ValueDisplayed: 750  (hidden comment: CRCW0603750RFKEA)
RES, 750, 1%, 0.1 W, 0603; Manufacturer: Vishay-Dale; CompType: Resistor; Value: 750; Value_Code: 750R; Tolerance_%: 1; Power_W: 0.1; Value2: 0.1W; VDC_V: 75; TempCo: 100 ppm/C; SizeArea_mm2: 1.28; SizeX_mm: 1.6; SizeY_mm: 0.8; EIA_Code: E96; U/M: EA; AEC Category: Q200
signal-integrity model Resistor
simulation model Resistor
footprint 0603
footprint 0603M
footprint 0603L
footprint 0603_HV
footprint 0603S
pins: 1, 2

## CRCW04020000Z0ED
designator R?  ValueDisplayed: 0  (hidden comment: CRCW04020000Z0ED)
RES, 0, 5%, 0.063 W, 0402; Manufacturer: Vishay-Dale; CompType: Resistor; Value: 0; Value_Code: 0000; Tolerance_%: 5; Power_W: 0.063; Value2: 0.063W; VDC_V: 50; TempCo: 200 ppm/C; SizeArea_mm2: 0.5; SizeX_mm: 1; SizeZ_mm: 0.6; EIA_Code: E24; U/M: EA; AEC Category: Q200
signal-integrity model Resistor
simulation model Resistor
footprint 0402
footprint 0402M
footprint 0402L
footprint 0402S
pins: 1, 2

## CRCW06030000Z0EA
designator R?  ValueDisplayed: 0  (hidden comment: CRCW06030000Z0EA)
RES, 0, 5%, 0.1 W, 0603; Manufacturer: Vishay-Dale; CompType: Resistor; Tolerance_%: 5; VDC_V: 75; Power_W: 0.1; Value: 0; U/M: EA; Value_Code: 0000; Value2: 0.1W; EIA_Code: E24; TempCo: 200 ppm/C; SizeArea_mm2: 1.28; SizeX_mm: 1.6; SizeY_mm: 0.8; SizeZ_mm: 1; AEC Category: Q200
signal-integrity model Resistor
simulation model Resistor
footprint 0603
footprint 0603M
footprint 0603L
footprint 0603_HV
footprint 0603S
pins: 1, 2

## CRCW08050000Z0EA
designator R?  ValueDisplayed: 0  (hidden comment: CRCW08050000Z0EA)
RES, 0, 5%, 0.125 W, 0805; Manufacturer: Vishay-Dale; CompType: Resistor; Value: 0; Value_Code: 0000; Tolerance_%: 5; Power_W: 0.125; Value2: 0.125W; VDC_V: 150; TempCo: 200 ppm/C; SizeArea_mm2: 2.5; SizeX_mm: 2; SizeY_mm: 1.25; SizeZ_mm: 1.45; EIA_Code: E24; U/M: EA; AEC Category: Q200; Green_Lifecycle: Active; Green_REACh: Passed
signal-integrity model Resistor
simulation model Resistor
footprint 0805_HV
footprint 0805_HV1
footprint 0805
footprint 0805M
footprint 0805L
pins: 1, 2

## CVHD-950-100.000
designator Y?  Frequency: 100 MHz  (hidden comment: CVHD-950-100.000)
VCXO, 100 MHz, 3.3V, SMD; Manufacturer: Crystek Corporation; SymbolCreator: a0412235; CompType: Oscillator; U/M: EA; TaMin_C: 0; TaMax_C: 70; Frequency Stability: ±20ppm
footprint OSC_CVHD-950-4
footprint OSC_CVHD-950-4_ExtPads
pins: 1 Vcont, 2 GND (power), 3 OUT, 4 Vcc (power)

## DIODE_SCHOTTKY
designator D?, comment B320B-13-F
Diode, Schottky, 20 V, 3 A, SMB; Manufacturer: Diodes Inc.; Io_A: 3A; Green_Lifecycle: Not Set; SizeAreaWB_mm2: 44.156; Vr_V: 20V; Green_REACh: Incomplete; TJmax_C: 125°C; U/M: EA; Value: 20V; SizeZ_mm: 2.6; SizeX_mm: 5.6; SizeY_mm: 3.81; Vf_V: 500mV; Value2: 0.5V; SizeArea_mm2: 21.336; AEC Category: Q101; RJC_CperW: 25
footprint SMB (Molded Diode, 2-Leads, Body 5.4x3.6mm, IPC Medium Density, based on OnSemi component dimensions)
pins: 1 K, 2 A

## DS90LV028AQMA
designator U?
Automotive LVDS Dual Differential Line Receiver, 8-pin Narrow SOIC; Manufacturer: Texas Instruments; PackageTopMarking: NSZXTT*90LV0*28AQM; PowerWise: N; CompType: Interface IC
footprint M08A_N (SOIC, 8-Leads, Body 4.9x3.9mm, Pitch 1.27mm, IPC Medium Density)
footprint M08A_L (SOIC, 8-Leads, Body 4.9x3.9mm, Pitch 1.27mm, IPC High Density)
footprint M08A_M (SOIC, 8-Leads, Body 4.9x3.9mm, Pitch 1.27mm, IPC Low Density)
pins: 1 RIN1- (in), 2 RIN1+ (in), 3 RIN2+ (in), 4 RIN2- (in), 5 GND (power), 6 ROUT2 (out), 7 ROUT1 (out), 8 VCC (power)

## EEPROM_8P
designator U?, comment 24LC512-I/ST
EEPROM, 512KBIT, 400KHZ, 8TSSOP; Manufacturer: Microchip; SizeAreaWB_mm2: 42; SizeZ_mm: 1.2; SizeX_mm: 6.4; SizeY_mm: 3; SizeArea_mm2: 19.2
footprint TSSOP-8 (TSSOP, 8-Leads, Body 3.1x4.5mm (max), Pitch 0.65mm, IPC Medium Density)
pins: 1 A0 (in), 2 A1 (in), 3 A2 (in), 4 VSS (power), 5 SDA (io), 6 SCL (in), 7 WP (in), 8 VCC (power)

## ERJ-1GN0R00C
designator R?  ValueDisplayed: 0  (hidden comment: ERJ-1GN0R00C)
RES, 0, 5%, 0.05 W, AEC-Q200 Grade 0, 0201; Manufacturer: Panasonic; CompType: Resistor; Tolerance_%: 5; Power_W: 0.05; Value: 0; U/M: EA; Value_Code: 0000; Value2: 0.05W; EIA_Code: E24; TempCo: ppm/C; SizeArea_mm2: 0.18; SizeX_mm: 0.6; SizeY_mm: 0.3; SizeZ_mm: 0.26; AEC Category: Q200; AEC Qualified: Y
signal-integrity model Resistor
simulation model Resistor
footprint 0201
footprint 0201M
footprint 0201L
footprint 0201_Silk
pins: 1, 2

## ERJ-2RKF1000X
designator R?  ValueDisplayed: 100  (hidden comment: ERJ-2RKF1000X)
RES, 100, 1%, 0.1 W, 0402; Manufacturer: Panasonic; CompType: Resistor; Value: 100; Value_Code: 100R; Tolerance_%: 1; Power_W: 0.1; Value2: 0.1W; VDC_V: 50; TempCo: 100 ppm/C; EIA_Code: E96; U/M: EA; AEC Category: Q200
signal-integrity model Resistor
simulation model Resistor
footprint 0402
footprint 0402M
footprint 0402L
footprint 0402S
pins: 1, 2

## ERJ-2RKF1002X
designator R?  ValueDisplayed: 10.0k  (hidden comment: ERJ-2RKF1002X)
RES, 10.0 k, 1%, 0.1 W, 0402; Manufacturer: Panasonic; CompType: Resistor; Value: 10.0k; Res_ohm: 10000; Value_Code: 10k0; Tolerance_%: 1; Power_W: 0.1; Value2: 0.1W; VDC_V: 50; TempCo: 100 ppm/C; SizeArea_mm2: 0.5; SizeZ_mm: 0.6; EIA_Code: E96; U/M: EA; AEC Category: Q200
signal-integrity model Resistor
simulation model Resistor
footprint 0402
footprint 0402M
footprint 0402L
footprint 0402S
pins: 1, 2

## ERJ-3EKF49R9V
designator R?  ValueDisplayed: 49.9  (hidden comment: ERJ-3EKF49R9V)
RES, 49.9, 1%, 0.1 W, AEC-Q200 Grade 0, 0603; Manufacturer: Panasonic; CompType: Resistor; Value: 49.9; Value_Code: 49R9; Tolerance_%: 1; Power_W: 0.1; Value2: 0.1W; TempCo: 100 ppm/C; SizeArea_mm2: 1.28; SizeX_mm: 1.6; SizeY_mm: 0.8; EIA_Code: E96; U/M: EA; AEC Category: Q200; AEC Qualified: Y; AEC Grade: 0; Green_Lifecycle: Active; Green_REACh: Passed
signal-integrity model Resistor
simulation model Resistor
footprint 0603
footprint 0603M
footprint 0603L
footprint 0603_HV
footprint 0603S
pins: 1, 2

## ERJ-3EKF1002V
designator R?  ValueDisplayed: 10.0k  (hidden comment: ERJ-3EKF1002V)
RES, 10.0 k, 1%, 0.1 W, 0603; Manufacturer: Panasonic; CompType: Resistor; Value: 10.0k; Res_ohm: 10000; Value_Code: 10k0; Tolerance_%: 1; Power_W: 0.1; Value2: 0.1W; VDC_V: 75; TempCo: 100 ppm/C; SizeArea_mm2: 1.28; SizeX_mm: 1.6; SizeY_mm: 0.8; EIA_Code: E96; U/M: EA; AEC Category: Q200; Green_Lifecycle: Active; Green_REACh: Passed
signal-integrity model Resistor
simulation model Resistor
footprint 0603
footprint 0603M
footprint 0603L
footprint 0603_HV
footprint 0603S
pins: 1, 2

## ERJ-6ENF2002V
designator R?  ValueDisplayed: 20.0k  (hidden comment: ERJ-6ENF2002V)
RES, 20.0 k, 1%, 0.125 W, 0805; Manufacturer: Panasonic; CompType: Resistor; Value: 20.0k; Res_ohm: 20000; Value_Code: 20k0; Tolerance_%: 1; Power_W: 0.125; Value2: 0.125W; TempCo: 100 ppm/C; SizeArea_mm2: 2.5; SizeX_mm: 2; SizeY_mm: 1.25; SizeZ_mm: 1.45; EIA_Code: E96; U/M: EA; AEC Category: Q200
signal-integrity model Resistor
simulation model Resistor
footprint 0805_HV
footprint 0805_HV1
footprint 0805
footprint 0805M
footprint 0805L
pins: 1, 2

## ERJ-6ENF4992V
designator R?  ValueDisplayed: 49.9k  (hidden comment: ERJ-6ENF4992V)
RES, 49.9 k, 1%, 0.125 W, 0805; Manufacturer: Panasonic; CompType: Resistor; Value: 49.9k; Res_ohm: 49900; Value_Code: 49k9; Tolerance_%: 1; Power_W: 0.125; Value2: 0.125W; TempCo: 100 ppm/C; SizeArea_mm2: 2.5; SizeX_mm: 2; SizeY_mm: 1.25; SizeZ_mm: 1.45; EIA_Code: E96; U/M: EA; AEC Category: Q200; Green_Lifecycle: Active; Green_REACh: Passed
signal-integrity model Resistor
simulation model Resistor
footprint 0805_HV
footprint 0805_HV1
footprint 0805
footprint 0805M
footprint 0805L
pins: 1, 2

## ESD_Susceptible
designator Logo?, comment ESD Susceptible  (value not drawn)  (no BOM)
ESD Susceptible Symbol; SymbolCreator: a0412235
footprint ESD_Overlay_SMALL
footprint ESD_Overlay_Medium
footprint ESD_Overlay_Small

## FC0402E50R0BST1
designator R?  ValueDisplayed: 50  (hidden comment: FC0402E50R0BST1)
RES, 50, 0.1%, 0.05 W, 0402; Manufacturer: Vishay-Dale; CompType: Resistor; Value: 50; Value_Code: 50R0; Tolerance_%: 0.1; Power_W: 0.05; Value2: 0.05W; TempCo: 25 ppm/C; U/M: EA; SizeArea_mm2: 0.5; SizeX_mm: 1; SizeZ_mm: 0.6; AEC Category: Q200; AEC Qualified: N
signal-integrity model Resistor
simulation model Resistor
footprint 0402
footprint 0402M
footprint 0402L
footprint 0402S
pins: 1, 2

## FCC_disclaimer
designator Logo?, comment FCC disclaimer  (no BOM)
FCC_disclaimer; SymbolCreator: codlsc
footprint FCC_disclaimer
footprint FCC_disclaimer_stacked

## Ferrite_Bead
designator L?, comment ValueDisplayed: 80 ohm  (hidden comment: CIM10U800NC)
Ferrite Bead, 80 ohm @ 100 MHz, 0.6 A, 0603; Manufacturer: Samsung Electro-Mechanics; ZTyp@100MHz_Ohm: 80; SizeAreaWB_mm2: 4.68; DCR_ohm: 0.1; Value1: 0.1 ohm; Value: 80 ohm; Imax_A: 600mA; SizeZ_mm: 1; SizeX_mm: 1.6; SizeY_mm: 0.8; Value2: 0.6A; SizeArea_mm2: 1.28
footprint 0603 (0603 from SM-752 data)
footprint 0603_HV (Ernesto recommended land pattern.  26 mil between pads.)
footprint 0603L (0603 from SM-752 data)
footprint 0603S
footprint 0603M (0603 from SM-752 data)
pins: 1, 2

## Fiducial
designator FID?  (value not drawn)
Fiducial mark.  There is nothing to buy or mount.; SymbolCreator: codlsc
footprint Fiducial10-30
footprint Fiducial10-20
footprint Fiducial15-30
footprint Fiducial20-40
footprint Fiducial6.4-20

## FT232HL-REEL
designator U?
Single Channel Hi-Speed USB to Multipurpose UART/FIFO IC, LQFP-48; Manufacturer: FTDI; SymbolCreator: Altium
footprint LQFP-48_N
footprint LQFP-48_L
footprint LQFP-48_M
pins: 1 XCSI (in), 2 XCSO (out), 3 VPHY (power), 4 AGND (power), 5 REF (in), 6 DM (in), 7 DP (in), 8 VPLL (power), 9 AGND (power), 10 GND (power), 11 GND (power), 12 VCCIO (power), 13 ADBUS0 (out), 14 ADBUS1 (in), 15 ADBUS2 (out), 16 ADBUS3 (in), 17 ADBUS4 (out), 18 ADBUS5 (in), 19 ADBUS6 (in), 20 ADBUS7 (in), 21 ACBUS0 (io), 22 GND (power), 23 GND (power), 24 VCCIO (power), 25 ACBUS1 (io), 26 ACBUS2 (io), 27 ACBUS3 (io), 28 ACBUS4 (io), 29 ACBUS5 (io), 30 ACBUS6 (io), 31 ACBUS7 (io), 32 ACBUS8 (io), 33 ACBUS9 (io), 34 ~{RESET} (in), 35 GND (power), 36 GND (power), 37 VCCA (power), 38 VCCCORE (power), 39 VCCD (power), 40 VREGIN (power), 41 AGND (power), 42 TEST (in), 43 EEDATA (io), 44 EECLK (out), 45 EECS (io), 46 VCCIO (power), 47 GND (power), 48 GND (power)

## GJM1555C1H270JB01
designator C?  ValueDisplayed: 27pF  (hidden comment: GJM1555C1H270JB01)
CAP, CERM, 27 pF, 50 V,+/- 5%, C0G/NP0, 0402; Manufacturer: MuRata; Polarized: N; CompType: Capacitor; Value: 27pF; U/M: EA; Cap_F: 0.000000000027; Tolerance_%: 5; VDC_V: 50; Value2: 50V; TaMin_C: -55; TaMax_C: 125; Cap_Case: 0402; SizeArea_mm2: 0.5; SizeAreaWB_mm2: 3; SizeX_mm: 1; SizeZ_mm: 0.6; AEC Category: Q200
signal-integrity model Cap
simulation model Cap
footprint 0402
footprint 0402M
footprint 0402L
footprint 0402S
pins: 1, 2

## GRM21BR72E103KW03L
designator C?  ValueDisplayed: 0.01µF  (hidden comment: GRM21BR72E103KW03L)
CAP, CERM, 0.01 µF, 250 V,+/- 10%, X7R, 0805; Manufacturer: MuRata; Polarized: N; CompType: Capacitor; Value: 0.01uF; U/M: EA; Cap_F: 0.00000001; Tolerance_%: 10; VDC_V: 250; Value2: 250V; TaMin_C: -55; TaMax_C: 125; Cap_Case: 0805; SizeArea_mm2: 2.5; SizeAreaWB_mm2: 6.75; SizeX_mm: 2; SizeY_mm: 1.25; SizeZ_mm: 1.45; AEC Category: Q200; Green_Lifecycle: Not Set; Green_REACh: Incomplete
signal-integrity model Cap
simulation model Cap
footprint 0805_HV
footprint 0805_HV1
footprint 0805
footprint 0805M
footprint 0805L
pins: 1, 2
